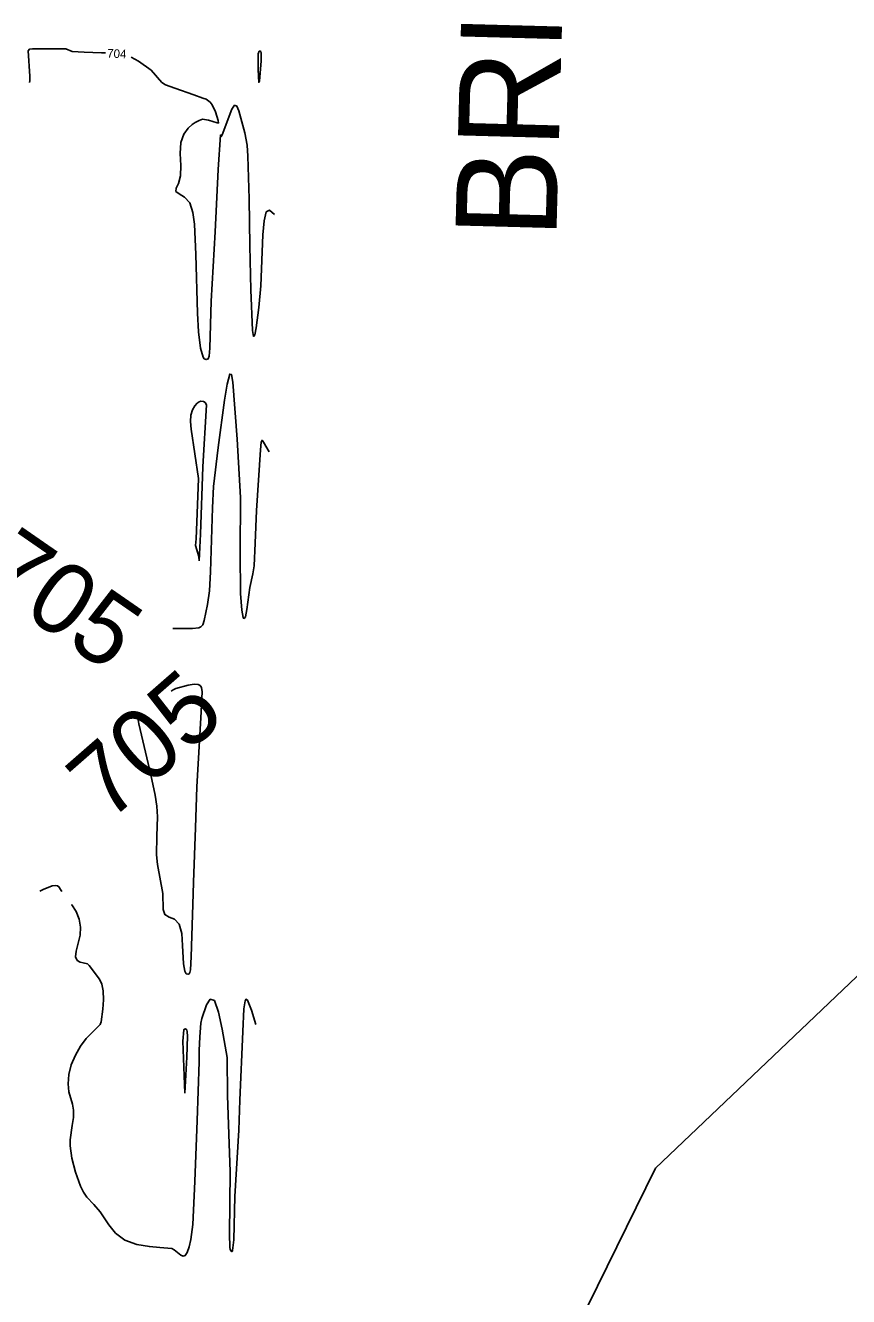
# Model space of a CAD drawing. Extents: x -291892836 to 2945206, y -477993085 to 1832792.
# Drawn here: x 1853987 to 1854368, y 544333 to 544921 of the extents above; entities that cross this region are included whole.
import ezdxf

# ---------------------------------------------------------------- set-up
doc = ezdxf.new("R2010")
doc.units = 0
for name, color, linetype in [('DT_X_Contour_Minor', 7, 'Continuous'), ('DT_X_Terrain_Ground_Line', 7, 'Continuous'), ('Level 19', 7, 'Continuous'), ('Level 40', 7, 'Continuous'), ('SC_Scratch1', 7, 'Continuous')]:
    doc.layers.add(name, color=color, linetype=linetype)

msp = doc.modelspace()

# ---------------------------------------------------------------- linework, layer by layer
at = {"layer": 'DT_X_Contour_Minor'}
for points in [[(1853988.74, 544894.97), (1853988.76, 544895.3), (1853988.89, 544895.45), (1853988.88, 544897.86), (1853988.13, 544909.6), (1853988.67, 544910.35), (1853990.13, 544910.52), (1854005.46, 544910.56), (1854008.49, 544909.3), (1854014.06, 544909.05), (1854021.99, 544908.79), (1854023.89, 544908.66)], [(1854095.14, 544909.5), (1854095.6, 544909.56), (1854095.89, 544909.33), (1854096.09, 544908.6), (1854096.03, 544904.93), (1854095.21, 544895.76), (1854094.92, 544895.02), (1854094.56, 544901), (1854094.59, 544908.2), (1854095.14, 544909.5)], [(1854035.81, 544906.73), (1854039.12, 544904.89), (1854045.09, 544900.69), (1854050, 544895), (1854051.68, 544893.93), (1854056.03, 544892.42), (1854064.87, 544889.3), (1854069.01, 544887.71), (1854070.48, 544887.33), (1854072.38, 544885.86), (1854073.33, 544884.62), (1854074.87, 544881.37), (1854076.11, 544877.31), (1854076.23, 544876.22), (1854075.7, 544876.24), (1854071.65, 544877.53), (1854068.8, 544878.02), (1854067.36, 544877.45), (1854066.34, 544876.85), (1854065.47, 544876.46), (1854064.09, 544875.56), (1854062.14, 544873.82), (1854060.16, 544871.06), (1854058.82, 544867.12), (1854058.55, 544862.03), (1854058.77, 544856.58), (1854058.65, 544851.75), (1854057.66, 544848.26), (1854056.57, 544845.98), (1854056.43, 544844.51), (1854057.96, 544843.41), (1854060.47, 544841.91), (1854062.9, 544839.2), (1854064.43, 544834.77), (1854065.17, 544829.36), (1854065.74, 544815.28), (1854066.52, 544788.17), (1854066.95, 544779.49), (1854067.97, 544771.99), (1854069.14, 544767.68), (1854069.65, 544766.92), (1854070.57, 544766.62), (1854071.5, 544766.97), (1854071.85, 544768.13), (1854072.19, 544771.89), (1854072.91, 544793.63), (1854074.71, 544825.83), (1854076.17, 544854.7), (1854077.1, 544870.71), (1854077.48, 544869.84), (1854077.99, 544870.76), (1854082.44, 544882.63), (1854083.72, 544884.46), (1854084.79, 544884.06), (1854085.71, 544881.88), (1854088.4, 544871.62), (1854089.5, 544866), (1854089.81, 544860.84), (1854090.45, 544841.16), (1854090.78, 544819.35), (1854091.16, 544798.99), (1854092.06, 544780.14), (1854092.52, 544777.39), (1854093.09, 544778.03), (1854093.73, 544781.26), (1854094.96, 544790.77), (1854095.84, 544800.76), (1854096.77, 544824.36), (1854097.37, 544830.84), (1854098.4, 544835.03), (1854099.94, 544835.77), (1854102.2, 544833.82)], [(1854055.11, 544642.12), (1854064.28, 544642.03), (1854067.17, 544642.4), (1854068.14, 544642.76), (1854068.93, 544643.69), (1854069.66, 544645.72), (1854071.16, 544653.14), (1854072.07, 544659.42), (1854072.48, 544668.31), (1854073.42, 544697.97), (1854073.91, 544707.8), (1854076.09, 544725.95), (1854079.07, 544747.83), (1854080.31, 544755.28), (1854081.44, 544759.91), (1854082.27, 544759.78), (1854082.85, 544756.12), (1854084.86, 544729.8), (1854086.37, 544702.74), (1854086.28, 544677.04), (1854086.39, 544658.28), (1854087, 544650.56), (1854087.62, 544647.12), (1854087.97, 544646.69), (1854088.33, 544646.88), (1854088.68, 544647.51), (1854089.4, 544650.88), (1854090.81, 544661.09), (1854092.17, 544667.33), (1854092.73, 544671.14), (1854093.27, 544681.6), (1854093.87, 544696.69), (1854095.78, 544724.84), (1854096.08, 544728.32), (1854096.45, 544729.23), (1854097.15, 544728.35), (1854099.67, 544723.92)], [(1854067.31, 544673.4), (1854067.85, 544685.8), (1854069.02, 544716.95), (1854070.64, 544745.72), (1854070.06, 544746.69), (1854069.33, 544747.23), (1854068.08, 544747.34), (1854067.35, 544747.09), (1854066.41, 544746.41), (1854065.28, 544745.15), (1854064.21, 544743.3), (1854063.49, 544740.9), (1854063.33, 544737.96), (1854063.66, 544734.33), (1854066.96, 544711.51), (1854066.57, 544699.3), (1854065.9, 544683.51), (1854065.66, 544680.49), (1854067.16, 544675.39), (1854067.31, 544673.4)], [(1854040.68, 544601.28), (1854038.98, 544599.8), (1854039.27, 544597.95), (1854044.94, 544574.27), (1854046.9, 544564.81), (1854047.62, 544559.71), (1854047.92, 544554.86), (1854047.69, 544545.84), (1854047.52, 544537.18), (1854047.94, 544532.78), (1854050.51, 544519.28), (1854050.62, 544511.8), (1854051.37, 544509.48), (1854053.32, 544508.36), (1854055.84, 544507.35), (1854058.02, 544505.11), (1854059.2, 544500.74), (1854059.62, 544495.27), (1854059.97, 544486.69), (1854060.67, 544483.36), (1854061.34, 544482.13), (1854062.16, 544481.88), (1854062.62, 544482.12), (1854063.01, 544482.73), (1854063.3, 544483.89), (1854063.66, 544489.9), (1854064.49, 544519.16), (1854064.68, 544524.46), (1854065.52, 544549.75), (1854066.22, 544568.72), (1854068.1, 544600.6), (1854068.7, 544612.75), (1854068.44, 544614.76), (1854067.82, 544615.64), (1854066.89, 544616.11), (1854065.01, 544616.29), (1854062.17, 544615.78), (1854056.41, 544614.25), (1854055.22, 544613.68), (1854054.34, 544613)], [(1854003.65, 544520.19), (1854003.33, 544520.6), (1854002.32, 544522.39), (1854001.66, 544522.85), (1854000.66, 544523.02), (1853999.22, 544522.79), (1853994.97, 544521.13), (1853993.43, 544520.43)], [(1854093.48, 544458.67), (1854091.55, 544465.21), (1854089.67, 544469.82), (1854089.04, 544470.27), (1854088.56, 544469.55), (1854087.98, 544465.89), (1854087.48, 544455.29), (1854086.17, 544423.56), (1854085.7, 544409.63), (1854083.83, 544378.96), (1854083.31, 544358.9), (1854082.81, 544353.83), (1854082.52, 544353.42), (1854082.21, 544353.44), (1854081.66, 544354.36), (1854081.48, 544355.41), (1854081.39, 544361.45), (1854081.62, 544390.4), (1854081.02, 544407.76), (1854080.49, 544425.68), (1854080.24, 544443.3), (1854077.96, 544456.42), (1854076.25, 544464.29), (1854074.35, 544469.66), (1854072.45, 544470.31), (1854070.75, 544467.68), (1854068.54, 544461.45), (1854068.05, 544459.26), (1854067.59, 544452.96), (1854067.24, 544446.5), (1854067.25, 544441.26), (1854066.41, 544414.14), (1854065.23, 544385.94), (1854064.33, 544365.92), (1854063.37, 544359.07), (1854062.59, 544355.61), (1854061.72, 544352.93), (1854060.82, 544351.55), (1854059.88, 544351.27), (1854058.84, 544351.72), (1854055.73, 544354.25), (1854054.67, 544354.88), (1854049.06, 544355.26), (1854044.21, 544355.69), (1854038.4, 544356.69), (1854032.87, 544358.7), (1854028.6, 544361.92), (1854025.52, 544365.72), (1854021.5, 544371.81), (1854018.52, 544375.2), (1854015.27, 544378.62), (1854013.69, 544380.89), (1854012.27, 544383.68), (1854009.95, 544390.19), (1854008.29, 544396.64), (1854007.53, 544402.37), (1854007.55, 544405.16), (1854008.49, 544411.8), (1854009.03, 544415.49), (1854009.15, 544418.89), (1854008.59, 544421.73), (1854006.87, 544427.35), (1854006.56, 544431.07), (1854006.91, 544435.37), (1854008.04, 544439.93), (1854009.96, 544444.45), (1854012.38, 544448.6), (1854014.93, 544452.08), (1854019.24, 544456.44), (1854021.48, 544458.56), (1854021.91, 544459.79), (1854022.65, 544465.71), (1854022.97, 544470.1), (1854022.89, 544474.21), (1854022.2, 544477.29), (1854021.08, 544479.54), (1854016.37, 544485.99), (1854015.56, 544486.65), (1854013.62, 544487.11), (1854012.15, 544487.44), (1854010.77, 544488.26), (1854010.05, 544489.92), (1854010.38, 544492.62), (1854012.11, 544499.92), (1854012.26, 544503.76), (1854011.66, 544507.45), (1854010.33, 544510.93), (1854008.36, 544514.09), (1854008.27, 544514.2)], [(1854060.66, 544426.86), (1854059.77, 544450.94), (1854060.12, 544456.13), (1854060.87, 544456.64), (1854061.24, 544456.49), (1854061.56, 544456.06), (1854061.81, 544455.19), (1854061.92, 544453.23), (1854061.6, 544443.52), (1854060.66, 544426.86)]]:
    msp.add_lwpolyline(points, dxfattribs=at)
at = {"layer": 'SC_Scratch1'}
msp.add_lwpolyline([(1847508.07, 542206.71), (1846998.91, 543896.83), (1851573.76, 547209.16), (1853501.81, 547291.67), (1855222.4, 545290.6), (1854278.63, 544392.05), (1853736.43, 543286.9), (1848894.08, 540466.94), (1848705.94, 540646.25)], close=True, dxfattribs=at)

# ---------------------------------------------------------------- texts
at = {"layer": 'DT_X_Terrain_Ground_Line'}
for rotation, p in [(325.33689, (1853964.61, 544663.22)), (41.16702, (1854025.1, 544551.89))]:
    msp.add_text('705', height=33, rotation=rotation, dxfattribs=at).set_placement(p)
at = {"layer": 'Level 19'}
msp.add_text('704', height=4, rotation=357.17616, dxfattribs=at).set_placement((1854024.58, 544906.58))
at = {"layer": 'Level 40'}
msp.add_text('BRIDGE LANE', height=46.8, rotation=88.45968, dxfattribs=at).set_placement((1854232.73, 544822.38))

doc.saveas('drawing.dxf')
